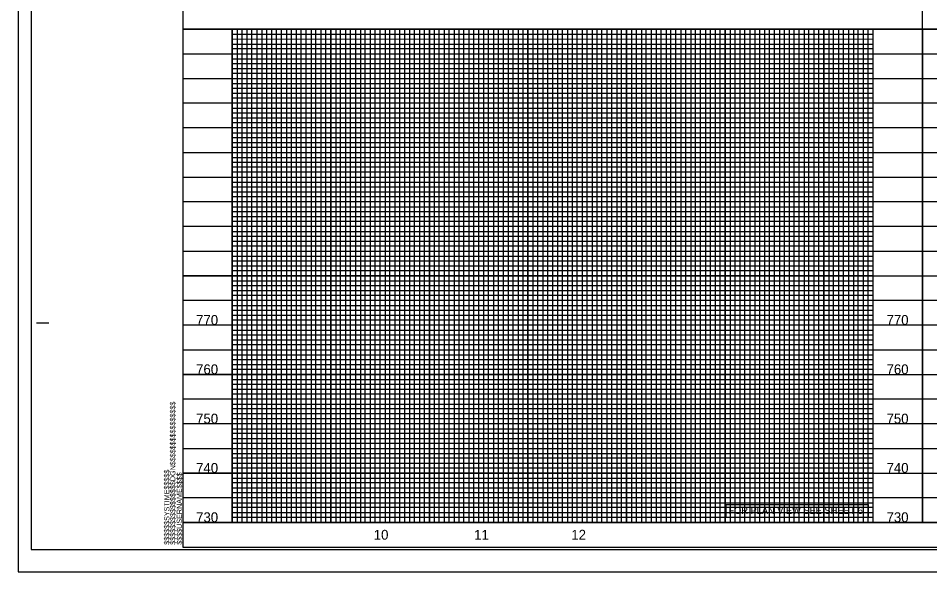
# Model space of a CAD drawing. Extents: x 1755181 to 1757273, y 729911 to 735411.
# Drawn here: x 1755181 to 1756105, y 729911 to 730472 of the extents above; entities that cross this region are included whole.
import ezdxf

# ---------------------------------------------------------------- set-up
doc = ezdxf.new("R2010")
doc.units = 0
for name, color, linetype in [('Exist Vertical Profile Horizontal Axis Label Major', 7, 'Continuous'), ('Exist Vertical Profile Vertical Axis Label', 7, 'Continuous'), ('Prop Grid Mask', 7, 'Continuous'), ('Prop VPI Label', 7, 'Continuous'), ('Scratch_Level_3', 7, 'Continuous'), ('Sheet Cutting Line CELL', 7, 'Continuous'), ('Sheet DOT Grid CELL', 7, 'Continuous'), ('Sheet Plot Border Inside CELL', 7, 'Continuous'), ('Sheet Plot Border Outside CELL', 7, 'Continuous'), ('Sheet Profile CELL', 7, 'Continuous'), ('Sheet Profile Grid Major CELL', 7, 'Continuous'), ('Sheet Profile Grid Middle CELL', 7, 'Continuous'), ('Sheet Profile Grid Minor CELL', 7, 'Continuous')]:
    doc.layers.add(name, color=color, linetype=linetype)

msp = doc.modelspace()

# ---------------------------------------------------------------- linework, layer by layer
at = {"layer": 'Prop Grid Mask'}
msp.add_lwpolyline([(1755898.53, 729978.99), (1756042.67, 729978.99), (1756042.67, 729965.78), (1755898.53, 729965.78)], close=True, dxfattribs=at)
at = {"layer": 'Scratch_Level_3'}
for points in [[(1755347.67, 730460.78), (1756097.67, 730460.78), (1756097.67, 730985.78), (1755347.67, 730985.78)], [(1756097.67, 730460.78), (1756097.67, 730985.78), (1756647.63, 730985.78), (1756647.63, 730752.66), (1756847.68, 730752.66), (1756847.68, 730460.78)], [(1755347.67, 729960.78), (1756097.67, 729960.78), (1756097.67, 730460.78), (1755347.67, 730460.78)], [(1756097.67, 729960.78), (1756847.67, 729960.78), (1756847.67, 730460.78), (1756097.67, 730460.78)]]:
    msp.add_lwpolyline(points, close=True, dxfattribs=at)
at = {"layer": 'Sheet Cutting Line CELL'}
for p, q in [((1755180.67, 731010.78), (1755180.67, 729910.78)), ((1755180.67, 729910.78), (1756864.67, 729910.78))]:
    msp.add_line(p, q, dxfattribs=at)
at = {"layer": 'Sheet DOT Grid CELL'}
for p, q in [((1755347.67, 730460.78), (1756847.56, 730460.78)), ((1755397.67, 729960.78), (1755397.67, 730460.78)), ((1755447.67, 729960.78), (1755447.67, 730460.78)), ((1755497.67, 729960.78), (1755497.67, 730460.78)), ((1755547.67, 729960.78), (1755547.67, 730460.78)), ((1755597.67, 729960.78), (1755597.67, 730460.78)), ((1755647.67, 729960.78), (1755647.67, 730460.78)), ((1755697.67, 729960.78), (1755697.67, 730460.78)), ((1755747.67, 729960.78), (1755747.67, 730460.78)), ((1755797.67, 729960.78), (1755797.67, 730460.78)), ((1755847.67, 729960.78), (1755847.67, 730460.78)), ((1755897.67, 729960.78), (1755897.67, 730460.78)), ((1755947.67, 729960.78), (1755947.67, 730460.78)), ((1755997.67, 729960.78), (1755997.67, 730460.78)), ((1756047.67, 729960.78), (1756047.67, 730460.78)), ((1756097.67, 729960.78), (1756097.67, 730460.78)), ((1756047.68, 730210.78), (1755347.67, 730210.78)), ((1756047.68, 730160.78), (1755347.67, 730160.78)), ((1756047.68, 730110.78), (1755347.67, 730110.78)), ((1756047.68, 730060.78), (1755347.67, 730060.78)), ((1756047.68, 730010.78), (1755347.67, 730010.78))]:
    msp.add_line(p, q, dxfattribs=at)
at = {"layer": 'Sheet Plot Border Inside CELL'}
msp.add_lwpolyline([(1755193.67, 729933.23), (1756860.17, 729933.23), (1756860.17, 730988.33), (1755193.67, 730988.33)], close=True, dxfattribs=at)
at = {"layer": 'Sheet Plot Border Outside CELL'}
msp.add_lwpolyline([(1755180.67, 729910.78), (1756864.67, 729910.78), (1756864.67, 731010.78), (1755180.67, 731010.78)], close=True, dxfattribs=at)
at = {"layer": 'Sheet Profile CELL'}
for p, q in [((1755347.67, 730460.78), (1756847.67, 730460.78)), ((1756097.67, 730460.78), (1756097.67, 729960.78)), ((1755199.17, 730163.28), (1755211.67, 730163.28)), ((1756847.67, 729960.78), (1755347.67, 729960.78)), ((1755347.67, 729935.78), (1756847.67, 729935.78)), ((1755347.67, 729935.78), (1755347.67, 729935.78))]:
    msp.add_line(p, q, dxfattribs=at)
msp.add_lwpolyline([(1756847.67, 730985.78), (1755347.67, 730985.78), (1755347.67, 729935.78), (1756847.67, 729935.78)], close=True, dxfattribs=at)
msp.add_lwpolyline([(1755385.17, 729935.78), (1755385.17, 729935.78)], dxfattribs=at)
at = {"layer": 'Sheet Profile Grid Major CELL'}
for p, q in [((1755847.67, 730460.78), (1755897.67, 730460.78)), ((1755947.67, 730460.78), (1755997.67, 730460.78)), ((1756047.67, 730460.78), (1756097.67, 730460.78)), ((1755347.67, 729960.78), (1755347.67, 729960.78))]:
    msp.add_line(p, q, dxfattribs=at)
for points in [[(1755397.67, 730460.78), (1755397.67, 729960.78), (1755447.67, 729960.78), (1755447.67, 730460.78), (1755497.67, 730460.78), (1755497.67, 729960.78), (1755547.67, 729960.78), (1755547.67, 730460.78), (1755597.67, 730460.78), (1755597.67, 729960.78), (1755647.67, 729960.78), (1755647.67, 730460.78), (1755697.67, 730460.78), (1755697.67, 729960.78), (1755747.67, 729960.78), (1755747.67, 730460.78), (1755797.67, 730460.78), (1755797.67, 729960.78), (1755847.67, 729960.78), (1755847.67, 730460.78), (1755897.67, 730460.78), (1755897.67, 729960.78), (1755947.67, 729960.78), (1755947.67, 730460.78), (1755997.67, 730460.78), (1755997.67, 729960.78), (1756047.67, 729960.78), (1756047.67, 730460.78), (1756097.67, 730460.78), (1756097.67, 729960.78), (1756147.67, 729960.78)], [(1755347.67, 730410.78), (1756847.71, 730410.78)], [(1756847.71, 730360.78), (1755347.67, 730360.78), (1755347.67, 730310.78), (1756847.71, 730310.78)], [(1756847.67, 730260.78), (1755347.67, 730260.78), (1755347.67, 730210.78), (1756847.67, 730210.78)], [(1756847.67, 730160.78), (1755347.67, 730160.78), (1755347.67, 730110.78), (1756847.67, 730110.78)], [(1756847.67, 730060.78), (1755347.67, 730060.78), (1755347.67, 730060.78), (1755347.67, 730010.78), (1756847.67, 730010.78)], [(1756847.67, 729960.78), (1755347.67, 729960.78)]]:
    msp.add_lwpolyline(points, dxfattribs=at)
at = {"layer": 'Sheet Profile Grid Middle CELL'}
for p, q in [((1755422.67, 730460.78), (1755422.67, 729960.78)), ((1755472.67, 729960.78), (1755472.67, 730460.78)), ((1755522.67, 730460.78), (1755522.67, 729960.78)), ((1755572.67, 729960.78), (1755572.67, 730460.78)), ((1755622.67, 730460.78), (1755622.67, 729960.78)), ((1755672.67, 729960.78), (1755672.67, 730460.78)), ((1755722.67, 730460.78), (1755722.67, 729960.78)), ((1755772.67, 729960.78), (1755772.67, 730460.78)), ((1755822.67, 730460.78), (1755822.67, 729960.78)), ((1755872.67, 729960.78), (1755872.67, 730460.78)), ((1755922.67, 730460.78), (1755922.67, 729960.78)), ((1755972.67, 729960.78), (1755972.67, 730460.78)), ((1756022.67, 730460.78), (1756022.67, 729960.78)), ((1755347.67, 730435.78), (1756847.66, 730435.78))]:
    msp.add_line(p, q, dxfattribs=at)
for points in [[(1756847.71, 730385.78), (1755347.67, 730385.78), (1755347.67, 730335.78), (1756847.71, 730335.78)], [(1756847.66, 730285.78), (1755347.67, 730285.78), (1755347.67, 730235.78), (1756847.67, 730235.78)], [(1756847.67, 730185.78), (1755347.67, 730185.78), (1755347.67, 730135.78), (1756847.67, 730135.78)], [(1756847.67, 730085.78), (1755347.67, 730085.78), (1755347.67, 730035.78), (1756847.67, 730035.78)], [(1756847.67, 729985.78), (1755347.67, 729985.78)]]:
    msp.add_lwpolyline(points, dxfattribs=at)
at = {"layer": 'Sheet Profile Grid Minor CELL'}
for p, q in [((1755927.67, 730460.78), (1755927.67, 729960.78)), ((1755932.67, 729960.78), (1755932.67, 730460.78)), ((1755937.67, 730460.78), (1755937.67, 729960.78)), ((1755942.67, 729960.78), (1755942.67, 730460.78)), ((1755952.67, 730460.78), (1755952.67, 729960.78)), ((1755957.67, 729960.78), (1755957.67, 730460.78)), ((1755962.67, 730460.78), (1755962.67, 729960.78)), ((1755967.67, 729960.78), (1755967.67, 730460.78)), ((1755977.67, 730460.78), (1755977.67, 729960.78)), ((1755982.67, 729960.78), (1755982.67, 730460.78)), ((1755987.67, 730460.78), (1755987.67, 729960.78)), ((1755992.67, 729960.78), (1755992.67, 730460.78)), ((1756002.67, 730460.78), (1756002.67, 729960.78)), ((1756007.67, 729960.78), (1756007.67, 730460.78)), ((1756012.67, 730460.78), (1756012.67, 729960.78)), ((1756017.67, 729960.78), (1756017.67, 730460.78)), ((1756027.67, 730460.78), (1756027.67, 729960.78)), ((1756032.67, 729960.78), (1756032.67, 730460.78)), ((1756037.67, 730460.78), (1756037.67, 729960.78)), ((1756042.67, 729960.78), (1756042.67, 730460.78)), ((1755397.67, 730455.78), (1756047.68, 730455.78)), ((1756047.68, 730450.62), (1755397.67, 730450.43)), ((1755397.67, 730445.78), (1756047.68, 730445.78)), ((1756047.68, 730325.78), (1755397.67, 730325.78)), ((1756047.68, 730320.78), (1755397.67, 730320.78)), ((1756047.68, 730315.78), (1755397.67, 730315.78)), ((1755397.67, 730305.78), (1756047.68, 730305.78)), ((1756047.68, 730300.78), (1755397.67, 730300.78)), ((1755397.67, 730295.78), (1756047.68, 730295.78)), ((1756047.68, 730275.78), (1755397.67, 730275.78)), ((1755397.67, 730270.78), (1756047.68, 730270.78)), ((1756047.68, 730250.78), (1755397.67, 730250.78)), ((1755397.67, 730245.78), (1756047.68, 730245.78)), ((1756047.68, 730225.78), (1755397.67, 730225.78)), ((1755397.67, 730220.78), (1756047.68, 730220.78)), ((1756047.68, 730215.78), (1755397.67, 730215.78)), ((1755397.67, 730205.78), (1756047.68, 730205.78)), ((1756047.68, 730200.78), (1755397.67, 730200.78)), ((1755397.67, 730195.78), (1756047.68, 730195.78)), ((1756047.68, 730190.78), (1755397.67, 730190.78)), ((1755397.67, 730180.78), (1756047.68, 730180.78)), ((1756047.68, 730175.78), (1755397.67, 730175.78)), ((1755397.67, 730170.78), (1756047.68, 730170.78)), ((1756047.68, 730165.78), (1755397.67, 730165.78)), ((1755397.67, 730155.78), (1756047.68, 730155.78)), ((1756047.68, 730150.78), (1755397.67, 730150.78)), ((1755397.67, 730145.78), (1756047.68, 730145.78)), ((1756047.68, 730140.78), (1755397.67, 730140.78)), ((1755397.67, 730130.78), (1756047.68, 730130.78)), ((1756047.68, 730125.78), (1755397.67, 730125.78)), ((1755397.67, 730120.78), (1756047.68, 730120.78)), ((1756047.68, 730115.78), (1755397.67, 730115.78)), ((1755397.67, 730105.78), (1756047.68, 730105.78)), ((1756047.68, 730100.78), (1755397.67, 730100.78)), ((1755397.67, 730095.78), (1756047.68, 730095.78)), ((1756047.68, 730090.78), (1755397.67, 730090.78)), ((1755397.67, 730080.78), (1756047.68, 730080.78)), ((1756047.68, 730075.78), (1755397.67, 730075.78)), ((1756047.68, 730070.78), (1755397.67, 730070.78)), ((1756047.68, 730065.78), (1755397.67, 730065.78)), ((1755397.67, 730055.78), (1756047.68, 730055.78)), ((1756047.68, 730050.78), (1755397.67, 730050.78)), ((1755397.67, 730045.78), (1756047.68, 730045.78)), ((1756047.68, 730040.78), (1755397.67, 730040.78)), ((1755397.67, 730030.78), (1756047.68, 730030.78)), ((1756047.68, 730025.78), (1755397.67, 730025.78)), ((1755397.67, 730020.78), (1756047.68, 730020.78)), ((1756047.68, 730015.78), (1755397.67, 730015.78)), ((1755397.67, 730005.78), (1756047.68, 730005.78)), ((1756047.68, 730000.78), (1755397.67, 730000.78)), ((1755397.67, 729995.78), (1756047.68, 729995.78)), ((1756047.68, 729990.78), (1755397.67, 729990.78)), ((1755397.67, 729980.78), (1756047.68, 729980.78)), ((1756047.68, 729975.78), (1755397.67, 729975.78)), ((1755397.67, 729970.78), (1756047.68, 729970.78))]:
    msp.add_line(p, q, dxfattribs=at)
for points in [[(1755402.67, 730460.78), (1755402.67, 729960.78), (1755407.67, 729960.78), (1755407.67, 730460.78), (1755412.67, 730460.78), (1755412.67, 729960.78), (1755417.67, 729960.78), (1755417.67, 730460.78), (1755427.67, 730460.78), (1755427.67, 729960.78), (1755432.67, 729960.78), (1755432.67, 730460.78), (1755437.67, 730460.78), (1755437.67, 729960.78), (1755442.67, 729960.78), (1755452.67, 729960.78), (1755457.67, 729960.78), (1755457.67, 730460.78), (1755462.67, 730460.78), (1755462.67, 729960.78), (1755467.67, 729960.78), (1755467.67, 730460.78), (1755477.67, 730460.78), (1755477.67, 729960.78), (1755482.67, 729960.78), (1755482.67, 730460.78), (1755487.67, 730460.78), (1755487.67, 729960.78), (1755492.67, 729960.78), (1755492.67, 730460.78), (1755502.67, 730460.78), (1755502.67, 729960.78), (1755507.67, 729960.78), (1755507.67, 730460.78), (1755512.67, 730460.78), (1755512.67, 729960.78), (1755517.67, 729960.78), (1755517.67, 730460.78), (1755527.67, 730460.78), (1755527.67, 729960.78), (1755532.67, 729960.78), (1755532.67, 730460.78), (1755537.67, 730460.78), (1755537.67, 729960.78), (1755542.67, 729960.78), (1755542.67, 730460.78), (1755552.67, 730460.78), (1755552.67, 729960.78), (1755557.67, 729960.78), (1755557.67, 730460.78), (1755562.67, 730460.78), (1755562.67, 729960.78), (1755567.67, 729960.78), (1755567.67, 730460.78), (1755577.67, 730460.78), (1755577.67, 729960.78), (1755582.67, 729960.78), (1755582.67, 730460.78), (1755587.67, 730460.78), (1755587.67, 729960.78), (1755592.67, 729960.78), (1755592.67, 730460.78), (1755602.67, 730460.78), (1755602.67, 729960.78), (1755607.67, 729960.78), (1755607.67, 730460.78), (1755612.67, 730460.78), (1755612.67, 729960.78)], [(1755442.67, 729960.78), (1755442.67, 730460.78), (1755452.67, 730460.78), (1755452.67, 729960.78)], [(1755612.67, 729960.78), (1755617.67, 729960.78), (1755617.67, 730460.78), (1755627.67, 730460.78), (1755627.67, 729960.78), (1755632.67, 729960.78), (1755632.67, 730460.78), (1755637.67, 730460.78), (1755637.67, 729960.78), (1755642.67, 729960.78), (1755642.67, 730460.78), (1755652.67, 730460.78), (1755652.67, 729960.78), (1755657.67, 729960.78), (1755657.67, 730460.78), (1755662.67, 730460.78), (1755662.67, 729960.78), (1755667.67, 729960.78), (1755667.67, 730460.78), (1755677.67, 730460.78), (1755677.67, 729960.78), (1755682.67, 729960.78), (1755682.67, 730460.78), (1755687.67, 730460.78), (1755687.67, 729960.78), (1755692.67, 729960.78), (1755692.67, 730460.78), (1755702.67, 730460.78), (1755702.67, 729960.78), (1755707.67, 729960.78), (1755707.67, 730460.78), (1755712.67, 730460.78), (1755712.67, 729960.78), (1755717.67, 729960.78), (1755717.67, 730460.78), (1755727.67, 730460.78), (1755727.67, 729960.78), (1755732.67, 729960.78), (1755732.67, 730460.78), (1755737.67, 730460.78), (1755737.67, 729960.78), (1755742.67, 729960.78), (1755742.67, 730460.78), (1755752.67, 730460.78), (1755752.67, 729960.78), (1755757.67, 729960.78), (1755757.67, 730460.78), (1755762.67, 730460.78), (1755762.67, 729960.78), (1755767.67, 729960.78), (1755767.67, 730460.78), (1755777.67, 730460.78), (1755777.67, 729960.78), (1755782.67, 729960.78), (1755782.67, 730460.78), (1755787.67, 730460.78), (1755787.67, 729960.78), (1755792.67, 729960.78), (1755792.67, 730460.78), (1755802.67, 730460.78), (1755802.67, 729960.78), (1755807.67, 729960.78), (1755807.67, 730460.78), (1755812.67, 730460.78), (1755812.67, 729960.78), (1755817.67, 729960.78), (1755817.67, 730460.78), (1755827.67, 730460.78), (1755827.67, 729960.78), (1755832.67, 729960.78), (1755832.67, 730460.78), (1755837.67, 730460.78), (1755837.67, 729960.78), (1755842.67, 729960.78), (1755842.67, 730460.78), (1755852.67, 730460.78), (1755852.67, 729960.78), (1755857.67, 729960.78), (1755857.67, 730460.78), (1755862.67, 730460.78), (1755862.67, 729960.78), (1755867.67, 729960.78), (1755867.67, 730460.78), (1755877.67, 730460.78), (1755877.67, 729960.78), (1755882.67, 729960.78), (1755882.67, 730460.78), (1755887.67, 730460.78), (1755887.67, 729960.78), (1755892.67, 729960.78), (1755892.67, 730460.78), (1755902.67, 730460.78), (1755902.67, 729960.78), (1755907.67, 729960.78), (1755907.67, 730460.78), (1755912.67, 730460.78), (1755912.67, 729960.78), (1755917.67, 729960.78), (1755917.67, 730460.78), (1755927.67, 730460.78)], [(1756047.68, 730440.78), (1755397.67, 730440.78), (1755397.67, 730430.78), (1756047.68, 730430.78)], [(1756047.68, 730425.78), (1755397.67, 730425.78), (1755397.67, 730420.78), (1756047.68, 730420.78)], [(1756047.68, 730415.78), (1755397.67, 730415.78), (1755397.67, 730405.78), (1756047.68, 730405.78)], [(1756047.68, 730400.78), (1755397.67, 730400.78), (1755397.67, 730395.78), (1756047.68, 730395.78)], [(1756047.68, 730390.78), (1755397.67, 730390.78), (1755397.67, 730380.78), (1756047.68, 730380.78)], [(1756047.68, 730375.78), (1755397.67, 730375.78), (1755397.67, 730370.78), (1756047.68, 730370.78)], [(1756047.68, 730365.78), (1755397.67, 730365.78), (1755397.67, 730355.78), (1756047.68, 730355.78)], [(1756047.68, 730350.68), (1755397.77, 730350.68), (1755397.77, 730345.78), (1756047.68, 730345.78)], [(1756047.68, 730340.78), (1755397.67, 730340.78), (1755397.67, 730330.78), (1756047.68, 730330.78)], [(1756047.68, 730290.78), (1755397.67, 730290.78), (1755397.67, 730280.78), (1756047.68, 730280.78)], [(1756047.68, 730265.78), (1755397.67, 730265.78), (1755397.67, 730255.78), (1756047.68, 730255.78)], [(1756047.68, 730240.78), (1755397.67, 730240.78), (1755397.67, 730230.78), (1756047.68, 730230.78)], [(1756047.68, 729965.78), (1755397.67, 729965.78)]]:
    msp.add_lwpolyline(points, dxfattribs=at)

# ---------------------------------------------------------------- texts
at = {"layer": 'Exist Vertical Profile Horizontal Axis Label Major'}
for s, p in [('10', (1755541.25, 729943.28)), ('11', (1755643.09, 729943.28)), ('12', (1755741.64, 729943.28))]:
    msp.add_text(s, height=10, dxfattribs=at).set_placement(p)
at = {"layer": 'Exist Vertical Profile Vertical Axis Label'}
for s, p in [('770', (1755361.1, 730161.03)), ('770', (1756061.33, 730161.03)), ('760', (1755361.1, 730111.03)), ('760', (1756061.33, 730111.03)), ('750', (1755361.1, 730061.03)), ('750', (1756061.33, 730061.03)), ('740', (1755361.1, 730011.03)), ('740', (1756061.33, 730011.03)), ('730', (1755361.1, 729961.03)), ('730', (1756061.33, 729961.03))]:
    msp.add_text(s, height=10, dxfattribs=at).set_placement(p)
at = {"layer": 'Prop VPI Label'}
msp.add_text('FOR PLAN VIEW SEE SHEET 6', height=7, dxfattribs=at).set_placement((1755901.07, 729969.37))
at = {"layer": 'Sheet Profile CELL'}
for s, p in [('$$$$$$$$$$$$$$$$DGN$$$$$$$$$$$$$$$$', (1755340.03, 729938.16)), ('$$$$$$SYSTIME$$$$$', (1755333.98, 729938.16)), ('$$$$USERNAME$$$$', (1755346.61, 729938.17))]:
    msp.add_text(s, height=5.25, rotation=90, dxfattribs=at).set_placement(p)

doc.saveas('drawing.dxf')
